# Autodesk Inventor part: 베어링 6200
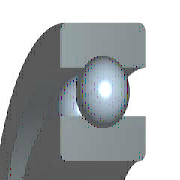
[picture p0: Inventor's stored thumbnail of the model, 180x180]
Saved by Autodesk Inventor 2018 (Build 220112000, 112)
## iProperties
Created: 2012-02
Part Number: 베어링 6200
Material: 강철, 연강
Description: 깊은 그루브 볼 베어링
Document SubType Name: Modeling
Standard: KS B 2023
Designer: mduedu
Standards Organization: KS
Language: ko-KR
Size Designation: 6200 - 10 x 30 x 9
Categories: <MemberInstance><Categories><Category DisplayName="샤프트 부품" InternalName="7f7aeb1f-a693-4053-b835-cee3144e0d98" Mnemonic="SHFT"><Category DisplayName="베어링" Inter
Density: 1 g/cm^3
Appearance: 노란색
IsCustomPart: 1
Author: mduedu
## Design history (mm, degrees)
sketch "스케치" dims "d0" = 5.2 (= -0.26 x WD + 0.26 x BD)
  geometry: L1 (1.9, 10)-(7.1, 10); L2 (4.5, 10)-(4.5, 7.4); L3 (4.5, 10)-(4.5, 12.6); L4 (2.568, 8.26)-(0, 8.26); L5 (0, 5)-(9, 5); L6 (2.568, 11.74)-(0, 11.74); L7 (0, 15)-(9, 15); L8 (9, 5)-(9, 8.26); L9 (6.432, 8.26)-(9, 8.26); L10 (6.432, 11.74)-(9, 11.74); L11 (9, 15)-(9, 11.74); L12 (-1.4, 0)-(8.4, 0) reference; L13 (0, -0.3)-(0, 5.3) reference
  constraints: 22 end point, 4 point on line, 2 collinear, 2 perpendicular, 2 symmetric about line, 1 midpoint, 1 parallel, 14 other
  dimensions: "d9" = 10 diameter of L5 L12 (= WD); "d11" = 30 diameter of L7 L12 (= BD); "d12" = 9 distance between parallel lines of L8 L13 (= KB); "d13" = 16.52 diameter of L9 L12 (= 0.326 x BD + 0.674 x WD)
revolve "본체" stored, may be unused: angle "d6" = 90 deg
revolve "볼" stored, may be unused: angle "d7" = 90 deg
pattern_circular "IDS_ARRAYBALL[SIMPL:T]" dims angle "d3" = 360 deg
body "Solid1"
fillet "모깎기1" dims "d1" = 0.6 (= KRS)
other parameters: "WD" = 10 [user parameter; used in 5 equation terms], "BD" = 30 [user parameter; used in 5 equation terms], "KB" = 9 [user parameter; used in 1 equation term], "KRS" = 0.6 [user parameter; used in 1 equation term], "d4" = 0, "d5" = 0, "d8" = 0, "d14" = 0, "d15" = 0, "BBA" = 0 [user parameter], "BC0" = 2360000 [user parameter], "BC" = 5070000 [user parameter], "BR" = 15 (= 0.5 x BD) [user parameter], "WR" = 5 (= 0.5 x WD) [user parameter]
